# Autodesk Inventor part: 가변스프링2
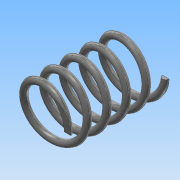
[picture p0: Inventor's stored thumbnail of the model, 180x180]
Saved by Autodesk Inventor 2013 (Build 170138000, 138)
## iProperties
Created: 2018-10
Part Number: 가변스프링2
Material: 스테인리스강
Document SubType Name: Modeling
Designer: Administrator
Density: 8.08 g/cm^3
Mass: 6.29163 g
Surface Area: 15.7915 cm^2
Volume: 0.778667 cm^3
Author: Administrator
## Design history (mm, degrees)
sketch "스케치1"
  geometry: L1 (0, 0)-(8, 0); L2 (0, 0)-(0, 29.48); L3 (0, 29.48)-(8, 29.48); C1 r 1 at (8, 0)
  constraints: 6 end point, 2 perpendicular, 1 centre point, 1 coincident, 1 horizontal
  dimensions: "d0" = 8 distance of L1.start L1.end; "d1" = 29.4802 distance of L1.start L2.end (derived); "d2" = 8 distance of L2.end L3.end; "d3" = 2 diameter of C1
feature "코일1" sketch "스케치1" pitch "d4" = 10; turns "d6" = 5; dims "d5" = 29.4802 (= d1), "d7" = 0, angle "d8" = 90 deg, angle "d9" = 90 deg, "d10" = 0, "d11" = 0
sketch "스케치2"
  geometry: L1 (29.48, 9.5)-(0, 9.5); L2 (0, 9.5)-(0, -9.5); L3 (0, -9.5)-(29.48, -9.5); L4 (29.48, -9.5)-(29.48, 9.5); 2 further points
  constraints: 8 end point, 2 parallel, 1 coincident, 1 horizontal, 1 midpoint, 1 perpendicular
  dimensions: "d12" = 29.4802 distance from line of point (0, 0) L4 (derived); "d13" = 19 distance between parallel lines of L3 L1
extrude "돌출1" sketch "스케치2" stored distance "d14" = 0; taper "d15" = 0 deg
node "솔리드1"
